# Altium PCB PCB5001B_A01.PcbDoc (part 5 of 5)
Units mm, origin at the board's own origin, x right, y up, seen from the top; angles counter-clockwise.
Board outline 115 x 60 mm, 6 copper layers (Top Layer, GND Layer 2, Signal Layer 3, Signal Layer 4, VCC Layer 5, Bottom Layer), stack 1.555 mm thick; 370 components, 274 nets, 1305 pads, 1129 vias.
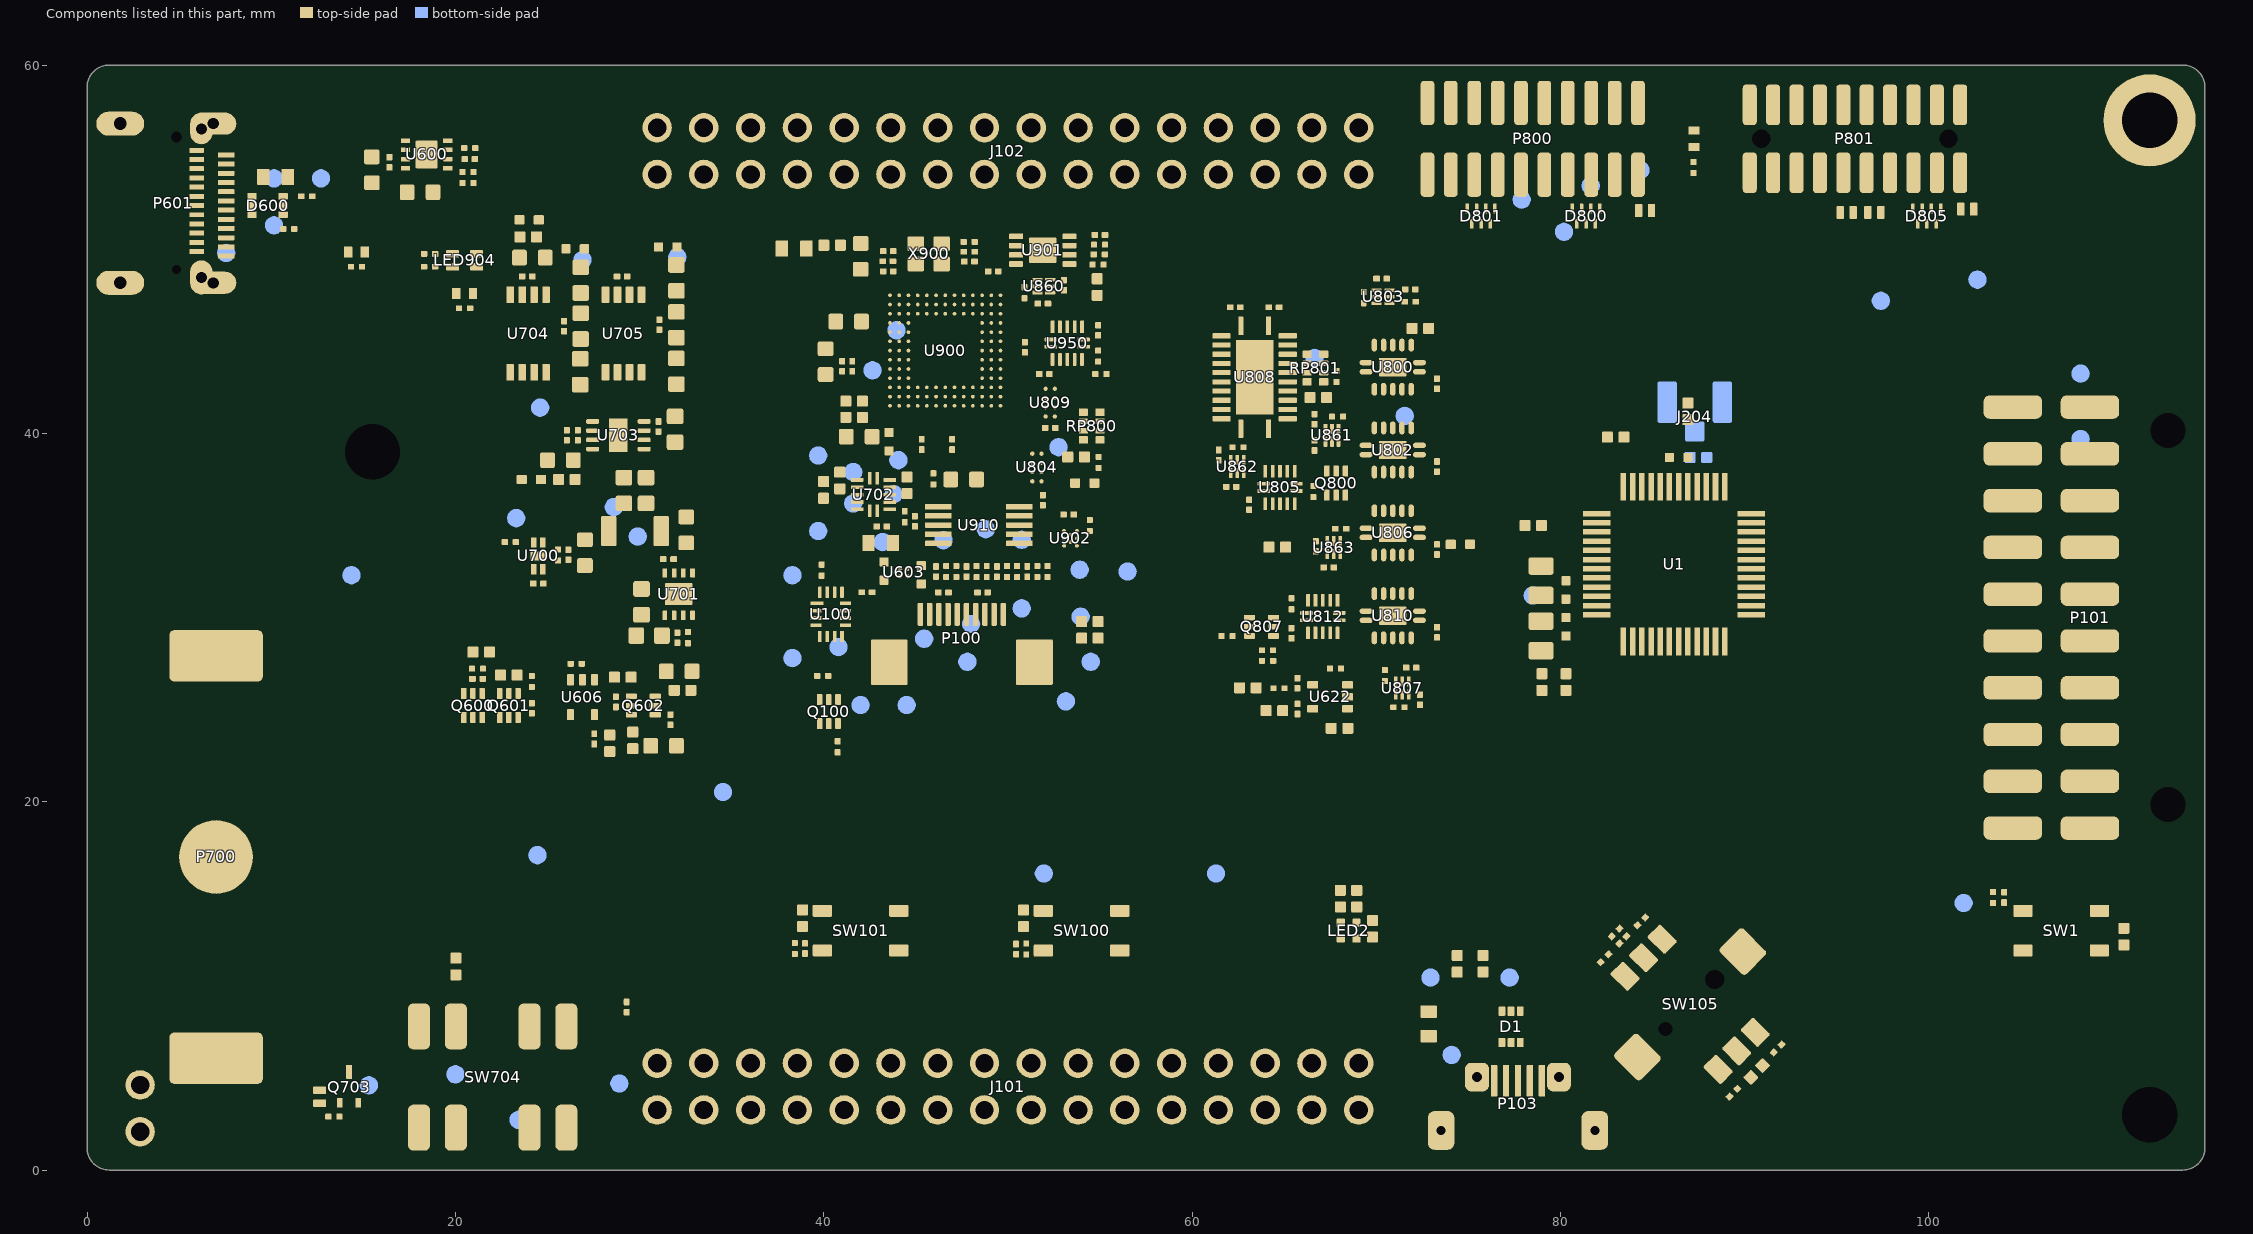
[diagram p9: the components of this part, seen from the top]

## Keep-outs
Bottom Layer:
  region: 12.7,54.35 cw(c12.7,53.85) 13.2,53.85 cw(c12.7,53.85) 12.7,53.35 cw(c12.7,53.85) 12.2,53.85 cw(c12.7,53.85)
  region: 32.691,5.802 ccw(c33.491,5.802) 33.491,5.002 ccw(c33.491,5.802) 34.291,5.802 ccw(c33.491,5.802) 33.491,6.602 ccw(c33.491,5.802)
  region: 35.231,5.802 ccw(c36.031,5.802) 36.031,5.002 ccw(c36.031,5.802) 36.831,5.802 ccw(c36.031,5.802) 36.031,6.602 ccw(c36.031,5.802)
  region: 37.771,5.802 ccw(c38.571,5.802) 38.571,5.002 ccw(c38.571,5.802) 39.371,5.802 ccw(c38.571,5.802) 38.571,6.602 ccw(c38.571,5.802)
  region: 40.311,5.802 ccw(c41.111,5.802) 41.111,5.002 ccw(c41.111,5.802) 41.911,5.802 ccw(c41.111,5.802) 41.111,6.602 ccw(c41.111,5.802)
  region: 42.851,5.802 ccw(c43.651,5.802) 43.651,5.002 ccw(c43.651,5.802) 44.451,5.802 ccw(c43.651,5.802) 43.651,6.602 ccw(c43.651,5.802)
  region: 45.391,5.802 ccw(c46.191,5.802) 46.191,5.002 ccw(c46.191,5.802) 46.991,5.802 ccw(c46.191,5.802) 46.191,6.602 ccw(c46.191,5.802)
  region: 47.931,5.802 ccw(c48.731,5.802) 48.731,5.002 ccw(c48.731,5.802) 49.531,5.802 ccw(c48.731,5.802) 48.731,6.602 ccw(c48.731,5.802)
  region: 50.471,5.802 ccw(c51.271,5.802) 51.271,5.002 ccw(c51.271,5.802) 52.071,5.802 ccw(c51.271,5.802) 51.271,6.602 ccw(c51.271,5.802)
  region: 53.011,5.802 ccw(c53.811,5.802) 53.811,5.002 ccw(c53.811,5.802) 54.611,5.802 ccw(c53.811,5.802) 53.811,6.602 ccw(c53.811,5.802)
  region: 55.551,5.802 ccw(c56.351,5.802) 56.351,5.002 ccw(c56.351,5.802) 57.151,5.802 ccw(c56.351,5.802) 56.351,6.602 ccw(c56.351,5.802)
  region: 58.091,5.802 ccw(c58.891,5.802) 58.891,5.002 ccw(c58.891,5.802) 59.691,5.802 ccw(c58.891,5.802) 58.891,6.602 ccw(c58.891,5.802)
  region: 60.631,5.802 ccw(c61.431,5.802) 61.431,5.002 ccw(c61.431,5.802) 62.231,5.802 ccw(c61.431,5.802) 61.431,6.602 ccw(c61.431,5.802)
  region: 63.171,5.802 ccw(c63.971,5.802) 63.971,5.002 ccw(c63.971,5.802) 64.771,5.802 ccw(c63.971,5.802) 63.971,6.602 ccw(c63.971,5.802)
  region: 65.711,5.802 ccw(c66.511,5.802) 66.511,5.002 ccw(c66.511,5.802) 67.311,5.802 ccw(c66.511,5.802) 66.511,6.602 ccw(c66.511,5.802)
  region: 68.251,5.802 ccw(c69.051,5.802) 69.051,5.002 ccw(c69.051,5.802) 69.851,5.802 ccw(c69.051,5.802) 69.051,6.602 ccw(c69.051,5.802)
  region: 30.151,5.802 ccw(c30.951,5.802) 30.951,5.002 ccw(c30.951,5.802) 31.751,5.802 ccw(c30.951,5.802) 30.951,6.602 ccw(c30.951,5.802)
  region: 30.151,3.262 ccw(c30.951,3.262) 30.951,2.462 ccw(c30.951,3.262) 31.751,3.262 ccw(c30.951,3.262) 30.951,4.062 ccw(c30.951,3.262)
  region: 30.151,3.262 ccw(c30.951,3.262) 30.951,2.462 ccw(c30.951,3.262) 31.751,3.262 ccw(c30.951,3.262) 30.951,4.062 ccw(c30.951,3.262)
  region: 32.691,3.262 ccw(c33.491,3.262) 33.491,2.462 ccw(c33.491,3.262) 34.291,3.262 ccw(c33.491,3.262) 33.491,4.062 ccw(c33.491,3.262)
  region: 35.231,3.262 ccw(c36.031,3.262) 36.031,2.462 ccw(c36.031,3.262) 36.831,3.262 ccw(c36.031,3.262) 36.031,4.062 ccw(c36.031,3.262)
  region: 37.771,3.262 ccw(c38.571,3.262) 38.571,2.462 ccw(c38.571,3.262) 39.371,3.262 ccw(c38.571,3.262) 38.571,4.062 ccw(c38.571,3.262)
  region: 40.311,3.262 ccw(c41.111,3.262) 41.111,2.462 ccw(c41.111,3.262) 41.911,3.262 ccw(c41.111,3.262) 41.111,4.062 ccw(c41.111,3.262)
  region: 42.851,3.262 ccw(c43.651,3.262) 43.651,2.462 ccw(c43.651,3.262) 44.451,3.262 ccw(c43.651,3.262) 43.651,4.062 ccw(c43.651,3.262)
  region: 45.391,3.262 ccw(c46.191,3.262) 46.191,2.462 ccw(c46.191,3.262) 46.991,3.262 ccw(c46.191,3.262) 46.191,4.062 ccw(c46.191,3.262)
  region: 47.931,3.262 ccw(c48.731,3.262) 48.731,2.462 ccw(c48.731,3.262) 49.531,3.262 ccw(c48.731,3.262) 48.731,4.062 ccw(c48.731,3.262)
  region: 50.471,3.262 ccw(c51.271,3.262) 51.271,2.462 ccw(c51.271,3.262) 52.071,3.262 ccw(c51.271,3.262) 51.271,4.062 ccw(c51.271,3.262)
  region: 53.011,3.262 ccw(c53.811,3.262) 53.811,2.462 ccw(c53.811,3.262) 54.611,3.262 ccw(c53.811,3.262) 53.811,4.062 ccw(c53.811,3.262)
  region: 55.551,3.262 ccw(c56.351,3.262) 56.351,2.462 ccw(c56.351,3.262) 57.151,3.262 ccw(c56.351,3.262) 56.351,4.062 ccw(c56.351,3.262)
  region: 58.091,3.262 ccw(c58.891,3.262) 58.891,2.462 ccw(c58.891,3.262) 59.691,3.262 ccw(c58.891,3.262) 58.891,4.062 ccw(c58.891,3.262)
  region: 60.631,3.262 ccw(c61.431,3.262) 61.431,2.462 ccw(c61.431,3.262) 62.231,3.262 ccw(c61.431,3.262) 61.431,4.062 ccw(c61.431,3.262)
  region: 63.171,3.262 ccw(c63.971,3.262) 63.971,2.462 ccw(c63.971,3.262) 64.771,3.262 ccw(c63.971,3.262) 63.971,4.062 ccw(c63.971,3.262)
  region: 65.711,3.262 ccw(c66.511,3.262) 66.511,2.462 ccw(c66.511,3.262) 67.311,3.262 ccw(c66.511,3.262) 66.511,4.062 ccw(c66.511,3.262)
  region: 68.251,3.262 ccw(c69.051,3.262) 69.051,2.462 ccw(c69.051,3.262) 69.851,3.262 ccw(c69.051,3.262) 69.051,4.062 ccw(c69.051,3.262)
  region: 32.691,56.602 ccw(c33.491,56.602) 33.491,55.802 ccw(c33.491,56.602) 34.291,56.602 ccw(c33.491,56.602) 33.491,57.402 ccw(c33.491,56.602)
  region: 35.231,56.602 ccw(c36.031,56.602) 36.031,55.802 ccw(c36.031,56.602) 36.831,56.602 ccw(c36.031,56.602) 36.031,57.402 ccw(c36.031,56.602)
  region: 37.771,56.602 ccw(c38.571,56.602) 38.571,55.802 ccw(c38.571,56.602) 39.371,56.602 ccw(c38.571,56.602) 38.571,57.402 ccw(c38.571,56.602)
  region: 40.311,56.602 ccw(c41.111,56.602) 41.111,55.802 ccw(c41.111,56.602) 41.911,56.602 ccw(c41.111,56.602) 41.111,57.402 ccw(c41.111,56.602)
  region: 42.851,56.602 ccw(c43.651,56.602) 43.651,55.802 ccw(c43.651,56.602) 44.451,56.602 ccw(c43.651,56.602) 43.651,57.402 ccw(c43.651,56.602)
  region: 45.391,56.602 ccw(c46.191,56.602) 46.191,55.802 ccw(c46.191,56.602) 46.991,56.602 ccw(c46.191,56.602) 46.191,57.402 ccw(c46.191,56.602)
  region: 47.931,56.602 ccw(c48.731,56.602) 48.731,55.802 ccw(c48.731,56.602) 49.531,56.602 ccw(c48.731,56.602) 48.731,57.402 ccw(c48.731,56.602)
  region: 50.471,56.602 ccw(c51.271,56.602) 51.271,55.802 ccw(c51.271,56.602) 52.071,56.602 ccw(c51.271,56.602) 51.271,57.402 ccw(c51.271,56.602)
  region: 53.011,56.602 ccw(c53.811,56.602) 53.811,55.802 ccw(c53.811,56.602) 54.611,56.602 ccw(c53.811,56.602) 53.811,57.402 ccw(c53.811,56.602)
  region: 55.551,56.602 ccw(c56.351,56.602) 56.351,55.802 ccw(c56.351,56.602) 57.151,56.602 ccw(c56.351,56.602) 56.351,57.402 ccw(c56.351,56.602)
  region: 58.091,56.602 ccw(c58.891,56.602) 58.891,55.802 ccw(c58.891,56.602) 59.691,56.602 ccw(c58.891,56.602) 58.891,57.402 ccw(c58.891,56.602)
  region: 60.631,56.602 ccw(c61.431,56.602) 61.431,55.802 ccw(c61.431,56.602) 62.231,56.602 ccw(c61.431,56.602) 61.431,57.402 ccw(c61.431,56.602)
  region: 63.171,56.602 ccw(c63.971,56.602) 63.971,55.802 ccw(c63.971,56.602) 64.771,56.602 ccw(c63.971,56.602) 63.971,57.402 ccw(c63.971,56.602)
  region: 65.711,56.602 ccw(c66.511,56.602) 66.511,55.802 ccw(c66.511,56.602) 67.311,56.602 ccw(c66.511,56.602) 66.511,57.402 ccw(c66.511,56.602)
  region: 68.251,56.602 ccw(c69.051,56.602) 69.051,55.802 ccw(c69.051,56.602) 69.851,56.602 ccw(c69.051,56.602) 69.051,57.402 ccw(c69.051,56.602)
  region: 30.151,56.602 ccw(c30.951,56.602) 30.951,55.802 ccw(c30.951,56.602) 31.751,56.602 ccw(c30.951,56.602) 30.951,57.402 ccw(c30.951,56.602)
  region: 30.151,54.062 ccw(c30.951,54.062) 30.951,53.262 ccw(c30.951,54.062) 31.751,54.062 ccw(c30.951,54.062) 30.951,54.862 ccw(c30.951,54.062)
  region: 30.151,54.062 ccw(c30.951,54.062) 30.951,53.262 ccw(c30.951,54.062) 31.751,54.062 ccw(c30.951,54.062) 30.951,54.862 ccw(c30.951,54.062)
  region: 32.691,54.062 ccw(c33.491,54.062) 33.491,53.262 ccw(c33.491,54.062) 34.291,54.062 ccw(c33.491,54.062) 33.491,54.862 ccw(c33.491,54.062)
  region: 35.231,54.062 ccw(c36.031,54.062) 36.031,53.262 ccw(c36.031,54.062) 36.831,54.062 ccw(c36.031,54.062) 36.031,54.862 ccw(c36.031,54.062)
  region: 37.771,54.062 ccw(c38.571,54.062) 38.571,53.262 ccw(c38.571,54.062) 39.371,54.062 ccw(c38.571,54.062) 38.571,54.862 ccw(c38.571,54.062)
  region: 40.311,54.062 ccw(c41.111,54.062) 41.111,53.262 ccw(c41.111,54.062) 41.911,54.062 ccw(c41.111,54.062) 41.111,54.862 ccw(c41.111,54.062)
  region: 42.851,54.062 ccw(c43.651,54.062) 43.651,53.262 ccw(c43.651,54.062) 44.451,54.062 ccw(c43.651,54.062) 43.651,54.862 ccw(c43.651,54.062)
  region: 45.391,54.062 ccw(c46.191,54.062) 46.191,53.262 ccw(c46.191,54.062) 46.991,54.062 ccw(c46.191,54.062) 46.191,54.862 ccw(c46.191,54.062)
  region: 47.931,54.062 ccw(c48.731,54.062) 48.731,53.262 ccw(c48.731,54.062) 49.531,54.062 ccw(c48.731,54.062) 48.731,54.862 ccw(c48.731,54.062)
  region: 50.471,54.062 ccw(c51.271,54.062) 51.271,53.262 ccw(c51.271,54.062) 52.071,54.062 ccw(c51.271,54.062) 51.271,54.862 ccw(c51.271,54.062)
  region: 53.011,54.062 ccw(c53.811,54.062) 53.811,53.262 ccw(c53.811,54.062) 54.611,54.062 ccw(c53.811,54.062) 53.811,54.862 ccw(c53.811,54.062)
  region: 55.551,54.062 ccw(c56.351,54.062) 56.351,53.262 ccw(c56.351,54.062) 57.151,54.062 ccw(c56.351,54.062) 56.351,54.862 ccw(c56.351,54.062)
  region: 58.091,54.062 ccw(c58.891,54.062) 58.891,53.262 ccw(c58.891,54.062) 59.691,54.062 ccw(c58.891,54.062) 58.891,54.862 ccw(c58.891,54.062)
  region: 60.631,54.062 ccw(c61.431,54.062) 61.431,53.262 ccw(c61.431,54.062) 62.231,54.062 ccw(c61.431,54.062) 61.431,54.862 ccw(c61.431,54.062)
  region: 63.171,54.062 ccw(c63.971,54.062) 63.971,53.262 ccw(c63.971,54.062) 64.771,54.062 ccw(c63.971,54.062) 63.971,54.862 ccw(c63.971,54.062)
  region: 65.711,54.062 ccw(c66.511,54.062) 66.511,53.262 ccw(c66.511,54.062) 67.311,54.062 ccw(c66.511,54.062) 66.511,54.862 ccw(c66.511,54.062)
  region: 68.251,54.062 ccw(c69.051,54.062) 69.051,53.262 ccw(c69.051,54.062) 69.851,54.062 ccw(c69.051,54.062) 69.051,54.862 ccw(c69.051,54.062)
  region: 45.391,54.062 ccw(c46.191,54.062) 46.191,53.262 ccw(c46.191,54.062) 46.991,54.062 ccw(c46.191,54.062) 46.191,54.862 ccw(c46.191,54.062)
  region: 42.851,54.062 ccw(c43.651,54.062) 43.651,53.262 ccw(c43.651,54.062) 44.451,54.062 ccw(c43.651,54.062) 43.651,54.862 ccw(c43.651,54.062)
  region: 40.311,54.062 ccw(c41.111,54.062) 41.111,53.262 ccw(c41.111,54.062) 41.911,54.062 ccw(c41.111,54.062) 41.111,54.862 ccw(c41.111,54.062)
  region: 37.771,54.062 ccw(c38.571,54.062) 38.571,53.262 ccw(c38.571,54.062) 39.371,54.062 ccw(c38.571,54.062) 38.571,54.862 ccw(c38.571,54.062)
  region: 35.231,54.062 ccw(c36.031,54.062) 36.031,53.262 ccw(c36.031,54.062) 36.831,54.062 ccw(c36.031,54.062) 36.031,54.862 ccw(c36.031,54.062)
  region: 32.691,54.062 ccw(c33.491,54.062) 33.491,53.262 ccw(c33.491,54.062) 34.291,54.062 ccw(c33.491,54.062) 33.491,54.862 ccw(c33.491,54.062)
  region: 30.151,54.062 ccw(c30.951,54.062) 30.951,53.262 ccw(c30.951,54.062) 31.751,54.062 ccw(c30.951,54.062) 30.951,54.862 ccw(c30.951,54.062)
  region: 30.151,54.062 ccw(c30.951,54.062) 30.951,53.262 ccw(c30.951,54.062) 31.751,54.062 ccw(c30.951,54.062) 30.951,54.862 ccw(c30.951,54.062)
  region: 30.151,56.602 ccw(c30.951,56.602) 30.951,55.802 ccw(c30.951,56.602) 31.751,56.602 ccw(c30.951,56.602) 30.951,57.402 ccw(c30.951,56.602)
  region: 45.391,56.602 ccw(c46.191,56.602) 46.191,55.802 ccw(c46.191,56.602) 46.991,56.602 ccw(c46.191,56.602) 46.191,57.402 ccw(c46.191,56.602)
  region: 42.851,56.602 ccw(c43.651,56.602) 43.651,55.802 ccw(c43.651,56.602) 44.451,56.602 ccw(c43.651,56.602) 43.651,57.402 ccw(c43.651,56.602)
  region: 40.311,56.602 ccw(c41.111,56.602) 41.111,55.802 ccw(c41.111,56.602) 41.911,56.602 ccw(c41.111,56.602) 41.111,57.402 ccw(c41.111,56.602)
  region: 37.771,56.602 ccw(c38.571,56.602) 38.571,55.802 ccw(c38.571,56.602) 39.371,56.602 ccw(c38.571,56.602) 38.571,57.402 ccw(c38.571,56.602)
  region: 35.231,56.602 ccw(c36.031,56.602) 36.031,55.802 ccw(c36.031,56.602) 36.831,56.602 ccw(c36.031,56.602) 36.031,57.402 ccw(c36.031,56.602)
  region: 32.691,56.602 ccw(c33.491,56.602) 33.491,55.802 ccw(c33.491,56.602) 34.291,56.602 ccw(c33.491,56.602) 33.491,57.402 ccw(c33.491,56.602)
  region: 68.251,3.262 ccw(c69.051,3.262) 69.051,2.462 ccw(c69.051,3.262) 69.851,3.262 ccw(c69.051,3.262) 69.051,4.062 ccw(c69.051,3.262)
  region: 65.711,3.262 ccw(c66.511,3.262) 66.511,2.462 ccw(c66.511,3.262) 67.311,3.262 ccw(c66.511,3.262) 66.511,4.062 ccw(c66.511,3.262)
  region: 60.631,3.262 ccw(c61.431,3.262) 61.431,2.462 ccw(c61.431,3.262) 62.231,3.262 ccw(c61.431,3.262) 61.431,4.062 ccw(c61.431,3.262)
  region: 58.091,3.262 ccw(c58.891,3.262) 58.891,2.462 ccw(c58.891,3.262) 59.691,3.262 ccw(c58.891,3.262) 58.891,4.062 ccw(c58.891,3.262)
  region: 40.311,3.262 ccw(c41.111,3.262) 41.111,2.462 ccw(c41.111,3.262) 41.911,3.262 ccw(c41.111,3.262) 41.111,4.062 ccw(c41.111,3.262)
  region: 37.771,3.262 ccw(c38.571,3.262) 38.571,2.462 ccw(c38.571,3.262) 39.371,3.262 ccw(c38.571,3.262) 38.571,4.062 ccw(c38.571,3.262)
  region: 35.231,3.262 ccw(c36.031,3.262) 36.031,2.462 ccw(c36.031,3.262) 36.831,3.262 ccw(c36.031,3.262) 36.031,4.062 ccw(c36.031,3.262)
  region: 32.691,3.262 ccw(c33.491,3.262) 33.491,2.462 ccw(c33.491,3.262) 34.291,3.262 ccw(c33.491,3.262) 33.491,4.062 ccw(c33.491,3.262)
  region: 30.151,3.262 ccw(c30.951,3.262) 30.951,2.462 ccw(c30.951,3.262) 31.751,3.262 ccw(c30.951,3.262) 30.951,4.062 ccw(c30.951,3.262)
  region: 30.151,3.262 ccw(c30.951,3.262) 30.951,2.462 ccw(c30.951,3.262) 31.751,3.262 ccw(c30.951,3.262) 30.951,4.062 ccw(c30.951,3.262)
  region: 30.151,5.802 ccw(c30.951,5.802) 30.951,5.002 ccw(c30.951,5.802) 31.751,5.802 ccw(c30.951,5.802) 30.951,6.602 ccw(c30.951,5.802)
  region: 68.251,5.802 ccw(c69.051,5.802) 69.051,5.002 ccw(c69.051,5.802) 69.851,5.802 ccw(c69.051,5.802) 69.051,6.602 ccw(c69.051,5.802)
  region: 65.711,5.802 ccw(c66.511,5.802) 66.511,5.002 ccw(c66.511,5.802) 67.311,5.802 ccw(c66.511,5.802) 66.511,6.602 ccw(c66.511,5.802)
  region: 63.171,5.802 ccw(c63.971,5.802) 63.971,5.002 ccw(c63.971,5.802) 64.771,5.802 ccw(c63.971,5.802) 63.971,6.602 ccw(c63.971,5.802)
  region: 60.631,5.802 ccw(c61.431,5.802) 61.431,5.002 ccw(c61.431,5.802) 62.231,5.802 ccw(c61.431,5.802) 61.431,6.602 ccw(c61.431,5.802)
  region: 58.091,5.802 ccw(c58.891,5.802) 58.891,5.002 ccw(c58.891,5.802) 59.691,5.802 ccw(c58.891,5.802) 58.891,6.602 ccw(c58.891,5.802)
  region: 40.311,5.802 ccw(c41.111,5.802) 41.111,5.002 ccw(c41.111,5.802) 41.911,5.802 ccw(c41.111,5.802) 41.111,6.602 ccw(c41.111,5.802)
  region: 37.771,5.802 ccw(c38.571,5.802) 38.571,5.002 ccw(c38.571,5.802) 39.371,5.802 ccw(c38.571,5.802) 38.571,6.602 ccw(c38.571,5.802)
  region: 35.231,5.802 ccw(c36.031,5.802) 36.031,5.002 ccw(c36.031,5.802) 36.831,5.802 ccw(c36.031,5.802) 36.031,6.602 ccw(c36.031,5.802)
  region: 32.691,5.802 ccw(c33.491,5.802) 33.491,5.002 ccw(c33.491,5.802) 34.291,5.802 ccw(c33.491,5.802) 33.491,6.602 ccw(c33.491,5.802)
  region: 103.5,19 cw(c103.5,18.5) 104,18.5 cw(c103.5,18.5) 103.5,18 cw(c103.5,18.5) 103,18.5 cw(c103.5,18.5)
  region: 108.25,40.2 cw(c108.25,39.699) 108.75,39.7 cw(c108.25,39.7) 108.25,39.2 cw(c108.25,39.7) 107.75,39.7 cw(c108.25,39.699)
  region: 108.25,43.748 cw(c108.25,43.248) 108.75,43.248 cw(c108.25,43.248) 108.25,42.748 cw(c108.25,43.248) 107.75,43.248 cw(c108.25,43.248)
  region: 107,54.2 cw(c107,53.7) 107.5,53.7 cw(c107,53.7) 107,53.2 cw(c107,53.7) 106.5,53.7 cw(c107,53.7)
  region: 105.4,52.498 cw(c105.4,51.998) 105.9,51.998 cw(c105.4,51.998) 105.4,51.498 cw(c105.4,51.998) 104.9,51.998 cw(c105.4,51.998)
  region: 104.45,54.2 cw(c104.45,53.7) 104.95,53.7 cw(c104.45,53.7) 104.45,53.2 cw(c104.45,53.7) 103.95,53.7 cw(c104.45,53.7)
  region: 103.399,52.498 cw(c103.399,51.998) 103.899,51.998 cw(c103.399,51.998) 103.399,51.498 cw(c103.399,51.998) 102.899,51.998 cw(c103.399,51.998)
  region: 102.649,48.848 cw(c102.649,48.348) 103.149,48.348 cw(c102.649,48.348) 102.649,47.848 cw(c102.649,48.348) 102.149,48.348 cw(c102.649,48.348)
  region: 97.399,47.7 cw(c97.399,47.2) 97.899,47.2 cw(c97.399,47.2) 97.399,46.7 cw(c97.399,47.2) 96.899,47.2 cw(c97.399,47.2)
  region: 92.525,52.432 cw(c92.525,51.932) 93.025,51.932 cw(c92.525,51.932) 92.525,51.432 cw(c92.525,51.932) 92.025,51.932 cw(c92.525,51.932)
  region: 93.541,54.21 cw(c93.541,53.71) 94.041,53.71 cw(c93.541,53.71) 93.541,53.21 cw(c93.541,53.71) 93.041,53.71 cw(c93.541,53.71)
  region: 90.493,52.432 cw(c90.493,51.932) 90.993,51.932 cw(c90.493,51.932) 90.493,51.432 cw(c90.493,51.932) 89.993,51.932 cw(c90.493,51.932)
  region: 88.461,52.432 cw(c88.461,51.932) 88.961,51.932 cw(c88.461,51.932) 88.461,51.432 cw(c88.461,51.932) 87.961,51.932 cw(c88.461,51.932)
  region: 89.477,54.21 cw(c89.477,53.71) 89.977,53.71 cw(c89.477,53.71) 89.477,53.21 cw(c89.477,53.71) 88.977,53.71 cw(c89.477,53.71)
  region: 87.466,54.206 cw(c87.467,53.706) 87.967,53.706 cw(c87.466,53.707) 87.466,53.206 cw(c87.466,53.706) 86.967,53.706 cw(c87.467,53.706)
  region: 84.349,54.799 cw(c84.349,54.299) 84.849,54.3 cw(c84.349,54.3) 84.349,53.799 cw(c84.349,54.299) 83.849,54.299 cw(c84.349,54.299)
  region: 85.4,52.198 cw(c85.4,51.698) 85.9,51.699 cw(c85.4,51.699) 85.4,51.199 cw(c85.4,51.698) 84.9,51.698 cw(c85.4,51.698)
  region: 93.449,42.798 cw(c93.45,42.298) 93.95,42.298 cw(c93.449,42.298) 93.449,41.798 cw(c93.449,42.298) 92.949,42.298 cw(c93.45,42.298)
  region: 86.15,40.05 cw(c86.15,39.55) 86.65,39.55 cw(c86.149,39.55) 86.149,39.05 cw(c86.149,39.55) 85.65,39.55 cw(c86.15,39.55)
  region: 81.649,53.949 cw(c81.649,53.449) 82.149,53.449 cw(c81.649,53.449) 81.649,52.949 cw(c81.649,53.449) 81.149,53.449 cw(c81.649,53.448)
  region: 77.9,53.199 cw(c77.9,52.699) 78.4,52.699 cw(c77.9,52.699) 77.9,52.199 cw(c77.9,52.699) 77.4,52.699 cw(c77.9,52.699)
  region: 80.201,51.449 cw(c80.201,50.949) 80.701,50.949 cw(c80.201,50.949) 80.201,50.449 cw(c80.201,50.949) 79.701,50.949 cw(c80.201,50.949)
  region: 77.399,48.498 cw(c77.399,47.998) 77.899,47.998 cw(c77.399,47.998) 77.399,47.498 cw(c77.399,47.998) 76.899,47.998 cw(c77.399,47.998)
  region: 75.4,48.498 cw(c75.4,47.998) 75.9,47.998 cw(c75.4,47.998) 75.4,47.498 cw(c75.4,47.998) 74.9,47.998 cw(c75.4,47.998)
  region: 73.399,48.498 cw(c73.399,47.998) 73.899,47.998 cw(c73.399,47.998) 73.399,47.498 cw(c73.399,47.998) 72.899,47.998 cw(c73.399,47.998)
  region: 77.399,46.298 cw(c77.399,45.798) 77.899,45.798 cw(c77.399,45.798) 77.399,45.298 cw(c77.399,45.798) 76.899,45.798 cw(c77.399,45.798)
  region: 75.4,46.298 cw(c75.4,45.798) 75.9,45.798 cw(c75.4,45.798) 75.4,45.298 cw(c75.4,45.798) 74.9,45.798 cw(c75.4,45.798)
  region: 73.399,46.298 cw(c73.399,45.798) 73.899,45.798 cw(c73.399,45.798) 73.399,45.298 cw(c73.399,45.798) 72.899,45.798 cw(c73.399,45.798)
  region: 71.4,46.298 cw(c71.4,45.798) 71.9,45.798 cw(c71.4,45.798) 71.4,45.298 cw(c71.4,45.798) 70.9,45.798 cw(c71.4,45.798)
  region: 73.399,43.598 cw(c73.399,43.098) 73.899,43.098 cw(c73.399,43.098) 73.399,42.598 cw(c73.399,43.098) 72.899,43.098 cw(c73.399,43.098)
  region: 71.55,41.449 cw(c71.55,40.949) 72.05,40.949 cw(c71.55,40.949) 71.55,40.449 cw(c71.55,40.949) 71.05,40.949 cw(c71.55,40.949)
  region: 66.65,44.599 cw(c66.65,44.099) 67.15,44.099 cw(c66.65,44.099) 66.65,43.599 cw(c66.65,44.099) 66.15,44.099 cw(c66.65,44.099)
  region: 94.199,12.348 cw(c94.199,11.848) 94.699,11.848 cw(c94.199,11.849) 94.199,11.348 cw(c94.199,11.848) 93.699,11.848 cw(c94.199,11.848)
  region: 96.8,11.8 cw(c96.8,11.3) 97.3,11.3 cw(c96.8,11.3) 96.8,10.8 cw(c96.8,11.3) 96.3,11.3 cw(c96.8,11.3)
  region: 93.249,9.948 cw(c93.249,9.448) 93.749,9.448 cw(c93.249,9.448) 93.249,8.948 cw(c93.249,9.448) 92.749,9.448 cw(c93.249,9.448)
  region: 96.5,9.148 cw(c96.5,8.648) 97,8.648 cw(c96.5,8.648) 96.5,8.148 cw(c96.5,8.648) 96,8.648 cw(c96.5,8.648)
  region: 95.7,6.55 cw(c95.7,6.05) 96.2,6.05 cw(c95.7,6.05) 95.7,5.55 cw(c95.7,6.05) 95.2,6.05 cw(c95.7,6.049)
  region: 93.249,7.398 cw(c93.249,6.898) 93.749,6.898 cw(c93.249,6.898) 93.249,6.398 cw(c93.249,6.898) 92.749,6.898 cw(c93.249,6.898)
  region: 81.499,10.949 cw(c81.499,10.449) 81.999,10.449 cw(c81.499,10.449) 81.499,9.949 cw(c81.499,10.449) 80.999,10.449 cw(c81.499,10.449)
  region: 77.249,10.949 cw(c77.249,10.449) 77.749,10.449 cw(c77.249,10.449) 77.249,9.949 cw(c77.249,10.449) 76.749,10.449 cw(c77.249,10.449)
  region: 72.949,10.949 cw(c72.949,10.449) 73.449,10.449 cw(c72.949,10.449) 72.949,9.949 cw(c72.949,10.449) 72.449,10.449 cw(c72.949,10.449)
  region: 74.1,6.748 cw(c74.1,6.248) 74.6,6.248 cw(c74.1,6.248) 74.1,5.748 cw(c74.1,6.248) 73.6,6.248 cw(c74.1,6.248)
  region: 54.674,41.624 cw(c54.674,41.124) 55.174,41.125 cw(c54.674,41.125) 54.674,40.625 cw(c54.674,41.124) 54.174,41.124 cw(c54.674,41.124)
  region: 52.749,39.75 cw(c52.749,39.25) 53.249,39.25 cw(c52.748,39.25) 52.748,38.75 cw(c52.748,39.25) 52.249,39.25 cw(c52.749,39.25)
  region: 50.75,34.723 cw(c50.75,34.223) 51.25,34.223 cw(c50.749,34.223) 50.75,33.723 cw(c50.75,34.223) 50.25,34.223 cw(c50.75,34.223)
  region: 53.899,33.098 cw(c53.899,32.598) 54.399,32.598 cw(c53.899,32.598) 53.899,32.098 cw(c53.899,32.598) 53.399,32.598 cw(c53.899,32.598)
  region: 50.75,31 cw(c50.75,30.5) 51.25,30.5 cw(c50.749,30.5) 50.75,30 cw(c50.75,30.5) 50.25,30.5 cw(c50.75,30.5)
  region: 53.95,30.55 cw(c53.95,30.05) 54.45,30.05 cw(c53.95,30.05) 53.95,29.55 cw(c53.95,30.05) 53.45,30.05 cw(c53.95,30.05)
  region: 54.499,28.099 cw(c54.499,27.599) 54.999,27.599 cw(c54.498,27.599) 54.499,27.099 cw(c54.499,27.599) 53.999,27.599 cw(c54.499,27.599)
  region: 51.799,28.099 cw(c51.799,27.599) 52.299,27.599 cw(c51.798,27.599) 51.799,27.099 cw(c51.799,27.599) 51.299,27.599 cw(c51.799,27.599)
  region: 53.15,25.95 cw(c53.15,25.45) 53.65,25.45 cw(c53.15,25.45) 53.15,24.95 cw(c53.15,25.45) 52.65,25.45 cw(c53.15,25.45)
  region: 47.999,30.149 cw(c47.999,29.649) 48.499,29.649 cw(c47.999,29.649) 47.999,29.149 cw(c47.999,29.649) 47.499,29.649 cw(c47.999,29.649)
  region: 45.449,29.349 cw(c45.449,28.849) 45.949,28.849 cw(c45.448,28.849) 45.449,28.349 cw(c45.449,28.849) 44.949,28.849 cw(c45.449,28.849)
  region: 47,25.749 cw(c47.001,25.249) 47.501,25.25 cw(c47,25.25) 47,24.75 cw(c47,25.249) 46.501,25.249 cw(c47.001,25.249)
  region: 43.249,28 cw(c43.249,27.5) 43.749,27.5 cw(c43.249,27.5) 43.249,27 cw(c43.249,27.5) 42.749,27.5 cw(c43.249,27.5)
  region: 44.499,25.749 cw(c44.499,25.249) 44.999,25.25 cw(c44.499,25.25) 44.499,24.75 cw(c44.499,25.249) 43.999,25.249 cw(c44.499,25.249)
  region: 41.999,25.749 cw(c41.999,25.249) 42.499,25.25 cw(c41.999,25.25) 41.999,24.75 cw(c41.999,25.249) 41.499,25.249 cw(c41.999,25.249)
  region: 61.301,16.598 cw(c61.301,16.098) 61.801,16.098 cw(c61.301,16.098) 61.301,15.598 cw(c61.301,16.098) 60.801,16.098 cw(c61.301,16.098)
  region: 51.951,16.598 cw(c51.951,16.098) 52.451,16.098 cw(c51.951,16.098) 51.951,15.598 cw(c51.951,16.098) 51.451,16.098 cw(c51.951,16.098)
  region: 34.524,21.025 cw(c34.524,20.525) 35.024,20.525 cw(c34.524,20.525) 34.524,20.025 cw(c34.524,20.525) 34.024,20.525 cw(c34.524,20.525)
  region: 24.45,17.599 cw(c24.45,17.099) 24.95,17.099 cw(c24.45,17.099) 24.45,16.599 cw(c24.45,17.099) 23.95,17.099 cw(c24.45,17.098)
  region: 15.649,26.448 cw(c15.649,25.948) 16.149,25.948 cw(c15.649,25.948) 15.649,25.448 cw(c15.649,25.948) 15.149,25.948 cw(c15.649,25.948)
  region: 12.05,26.448 cw(c12.05,25.948) 12.55,25.948 cw(c12.05,25.948) 12.05,25.448 cw(c12.05,25.948) 11.55,25.948 cw(c12.05,25.948)
  region: 12.025,29.773 cw(c12.025,29.273) 12.525,29.273 cw(c12.025,29.273) 12.025,28.773 cw(c12.025,29.273) 11.525,29.273 cw(c12.025,29.273)
  region: 9.475,29.798 cw(c9.475,29.298) 9.975,29.298 cw(c9.474,29.298) 9.475,28.798 cw(c9.475,29.298) 8.975,29.298 cw(c9.475,29.298)
  region: 14.349,32.798 cw(c14.349,32.298) 14.849,32.298 cw(c14.349,32.298) 14.349,31.798 cw(c14.349,32.298) 13.849,32.298 cw(c14.349,32.298)
  region: 10.399,32.249 cw(c10.399,31.749) 10.899,31.749 cw(c10.399,31.75) 10.399,31.249 cw(c10.399,31.749) 9.899,31.749 cw(c10.399,31.749)
  region: 10.399,34.899 cw(c10.399,34.399) 10.899,34.399 cw(c10.399,34.399) 10.399,33.899 cw(c10.399,34.399) 9.899,34.399 cw(c10.399,34.398)
  region: 18.446,49.044 cw(c18.446,48.544) 18.946,48.544 cw(c18.446,48.544) 18.446,48.044 cw(c18.446,48.544) 17.946,48.544 cw(c18.446,48.544)
  region: 15.906,50.314 cw(c15.906,49.814) 16.406,49.814 cw(c15.906,49.814) 15.906,49.314 cw(c15.906,49.814) 15.406,49.814 cw(c15.906,49.814)
  region: 18.446,51.584 cw(c18.446,51.084) 18.946,51.084 cw(c18.446,51.084) 18.446,50.584 cw(c18.446,51.084) 17.946,51.084 cw(c18.446,51.084)
  region: 15.906,52.854 cw(c15.906,52.354) 16.406,52.354 cw(c15.906,52.354) 15.906,51.854 cw(c15.906,52.354) 15.406,52.354 cw(c15.906,52.354)
  region: 18.446,54.124 cw(c18.446,53.624) 18.946,53.624 cw(c18.446,53.624) 18.446,53.124 cw(c18.446,53.624) 17.946,53.624 cw(c18.446,53.624)
  region: 15.906,55.394 cw(c15.906,54.894) 16.406,54.894 cw(c15.906,54.894) 15.906,54.394 cw(c15.906,54.894) 15.406,54.894 cw(c15.906,54.894)
  region: 10.15,54.35 cw(c10.15,53.85) 10.65,53.85 cw(c10.15,53.85) 10.15,53.35 cw(c10.15,53.85) 9.65,53.85 cw(c10.15,53.85)
  region: 10.15,51.8 cw(c10.15,51.3) 10.65,51.3 cw(c10.15,51.3) 10.15,50.8 cw(c10.15,51.3) 9.65,51.3 cw(c10.15,51.3)
  region: 7.549,50.299 cw(c7.549,49.799) 8.049,49.799 cw(c7.549,49.799) 7.549,49.299 cw(c7.549,49.799) 7.049,49.799 cw(c7.549,49.798)
  region: 24.6,41.899 cw(c24.6,41.399) 25.1,41.399 cw(c24.6,41.399) 24.6,40.899 cw(c24.6,41.399) 24.1,41.399 cw(c24.6,41.399)
  region: 36.249,37.548 cw(c36.249,37.048) 36.749,37.048 cw(c36.249,37.048) 36.249,36.548 cw(c36.249,37.048) 35.749,37.048 cw(c36.249,37.048)
  region: 38.999,37.548 cw(c39,37.048) 39.5,37.048 cw(c38.999,37.048) 38.999,36.548 cw(c38.999,37.048) 38.5,37.048 cw(c39,37.048)
  region: 41.6,38.399 cw(c41.6,37.899) 42.101,37.899 cw(c41.6,37.899) 41.6,37.399 cw(c41.6,37.899) 41.1,37.899 cw(c41.601,37.899)
  region: 44.049,39.049 cw(c44.049,38.549) 44.549,38.549 cw(c44.049,38.549) 44.049,38.049 cw(c44.049,38.549) 43.549,38.549 cw(c44.049,38.549)
  region: 42.649,43.923 cw(c42.65,43.423) 43.15,43.423 cw(c42.649,43.423) 42.649,42.923 cw(c42.649,43.423) 42.149,43.423 cw(c42.65,43.423)
  region: 43.95,46.1 cw(c43.95,45.6) 44.45,45.6 cw(c43.95,45.6) 43.95,45.1 cw(c43.95,45.6) 43.45,45.6 cw(c43.95,45.6)
  region: 18.446,46.504 cw(c18.446,46.004) 18.946,46.004 cw(c18.446,46.004) 18.446,45.504 cw(c18.446,46.004) 17.946,46.004 cw(c18.446,46.004)

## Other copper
Top Layer:
  pour cut-out: 30.625,27.725 30.875,27.475 31.075,27.475 31.075,27.45 31.025,27.4 30.7,27.725
  pour cut-out: 64.725,31.3 64.35,30.925 64.35,30.8 64.449,30.8 64.75,31.101 64.75,31.25
  pour cut-out: 65.452,31.453 65.749,31.75 66,31.75 66,31.65 66.025,31.625 65.825,31.425 65.48,31.425
  pour cut-out: 24.525,49.15 24.315,48.94 24.315,48.839 24.259,48.839 24.109,48.989 24.27,49.15 24.5,49.15
  pour cut-out: 38.15,50.5 38.625,50.5 38.75,50.375 38.65,50.275 38.65,49.55 38.35,49.55 38.15,49.75 38.15,50.475
  pour cut-out: 82.85,36.225 89.575,36.225 89.575,29.525 89.525,29.475 82.825,29.475 82.825,36.2 82.875,36.25
  region net 3V3: 102.16,43.21 101.55,42.6 101.55,41.475 102.24,40.785 105.985,40.785 106.175,40.975 106.175,42.75 105.715,43.21
  region net GND: 107.335,19.21 107.085,18.96 107.085,17.26 107.56,16.785 110.96,16.785 111.385,17.21 111.385,19.085 111.26,19.21
  pour cut-out: 110.05,21.75 110.025,21.725 110.25,21.725 110.25,22.75 110.05,22.95
  pour cut-out: 103.2,25.425 103.2,24.35 103.275,24.275 103.45,24.275 103.45,25.35 103.485,25.385 103.098,25.385
  pour cut-out: 109.9,24.35 110.15,24.35 110.05,24.45 110.05,25.525 109.975,25.525 109.9,25.45
  pour cut-out: 110.025,33.175 109.975,33.125 109.975,31.925 110.368,31.925 110.403,31.961 110.05,32.314 110.05,33.225
  pour cut-out: 31.7,24 31.7,23.525 31.781,23.444 32.004,23.444 32.004,24.02 31.989,24.035 31.954,24 31.675,24
  pour cut-out: 93.025,34.5 93.025,33.775 93.05,33.75 93.05,34.475
  pour cut-out: 80.55,25.775 80.548,25.773 80.548,25.002 80.927,25.002 80.95,25.025 80.525,25.45 80.525,25.75
  pour cut-out: 78.325,29.3 78.325,28.7 79.5,28.7 79.525,28.725 79.5,28.75 79.5,29.325 78.325,29.325 78.3,29.3
  pour cut-out: 78.475,32.325 78.475,31.725 78.45,31.7 78.475,31.675 79.5,31.675 79.5,32.325
  pour cut-out: 72.15,8.25 72.15,7.75 72.191,7.791 73.348,7.791 73.348,8.202 73.275,8.275 72.2,8.275
  pour cut-out: 44.7,50.825 44.675,50.85 44.675,51.575 44.525,51.425 44.625,51.325 44.625,50.825
  pour cut-out: 31.1,32.625 31.1,33.025 31.4,33.025 31.55,32.875 31.55,32.75 31.25,32.75 31.175,32.675
  pour cut-out: 32.025,33.625 31.95,33.55 31.95,33.475 32.1,33.325 32.175,33.325 32.175,33.625
  pour cut-out: 25.8,33.975 25.95,33.975 25.95,33.9 25.925,33.875 25.75,33.875 25.75,33.925
  pour cut-out: 27.575,34.125 27.8,34.125 27.8,33.875 27.775,33.85 27.75,33.875 27.6,33.875 27.6,34.1
  pour cut-out: 26.425,33.65 26.5,33.65 26.5,33.55 26.425,33.55
  pour cut-out: 26.35,33.975 26.525,33.975 26.525,33.9 26.475,33.85 26.375,33.85 26.375,33.95
  region net BC_I2C_EXP_SDA: 107.11,43.21 106.86,42.96 106.86,41.26 107.335,40.785 110.735,40.785 111.16,41.21 111.16,43.085 111.035,43.21
  region net VMCU: 102.175,19.2 101.925,18.95 101.925,17.25 102.4,16.775 105.8,16.775 106.225,17.2 106.225,19.075 106.1,19.2
  pour cut-out: 61.65,36.025 61.425,36.025 60.925,35.525 60.85,35.6 60.85,35.7 61,35.7 61.475,36.175
  pour cut-out: 41.075,46.95 41.125,46.9 41.125,46.5 41.55,46.5 41.6,46.55 41.425,46.725 41.425,47.1
  pour cut-out: 41.25,48.1 41.225,48.075 41.225,47.6 41.525,47.6 41.475,47.65 41.475,48.15 41.35,48.15 41.325,48.125
  pour cut-out: 40.05,40.075 40.05,40.175 40.55,40.675 40.5,40.725 40.225,40.725 40.225,40.575 39.85,40.2
  pour cut-out: 9.625,55.525 10.875,55.525 10.85,55.5 10.85,55.45 9.625,55.45 9.6,55.475
  pour cut-out: 23.95,32.4 23.95,32.05 24.1,32.05 24.1,32.4
  pour cut-out: 21.7,27.266 22.2,27.266 22.2,26.1 21.7,26.1
  region net N17710582: 10.542,26.275 10.542,29.5 3.462,29.5 3.462,26.275
  region net N17710582: 3.458,7.725 3.458,5.542 4.5,4.5 10.538,4.5 10.538,7.725
Signal Layer 3:
  pour cut-out: 36.575,54.8 38.05,54.8 38.05,54.475 38,54.425 37.975,54.45 36.575,54.45 36.575,54.75 36.6,54.775
  pour cut-out: 41.1,48.2 41.175,48.125 41.175,47.475 41.3,47.475 41.225,47.55 41.225,48.2 41.125,48.2
  pour cut-out: 92.018,31.557 91.925,31.464 91.925,30.975 92.05,30.975 92.018,31.007 92.018,31.543 91.95,31.475
  pour cut-out: 81.075,34.725 82.075,35.725 82.119,35.725 82.119,35.47 81.224,34.575 81.175,34.575 81.175,34.625
  pour cut-out: 80.15,48.525 80.15,47.85 80.425,47.85 80.425,48.5 80.375,48.55 80.35,48.525
  pour cut-out: 48.225,6.25 51.1,6.25 51.3,6.05 51.3,3.375 48.2,3.375 48.125,3.45 48.25,3.575 48.25,6.15
  pour cut-out: 64.375,3.525 64.275,3.425 64.2,3.5 51.225,3.5 51.225,6.225 51.275,6.275 64.375,6.275
  pour cut-out: 59.175,10.45 59.9,9.725 59.6,9.425 59.175,9.85 59.175,10.4
  pour cut-out: 61.625,13.2 61.575,13.15 61.575,11.9 61.65,11.9 61.675,11.925 61.675,13.225 61.625,13.225 61.6,13.2
  pour cut-out: 70.025,13.3 70.025,11.975 70.35,11.975 70.125,12.2 70.125,13.35
  pour cut-out: 54.3,51.3 54.1,51.1 54.1,50.7 54.125,50.7 54.3,50.525 54.373,50.598 54.498,50.598 54.498,51.152 54.35,51.3 54.275,51.3
  pour cut-out: 60.9,45.55 60.5,45.15 60.5,44.8 60.55,44.8 60.675,44.675 61.025,45.025 61.025,45.4 60.875,45.55
  pour cut-out: 83.075,45.975 83.05,45.95 83.05,44.75 83.225,44.75 83.225,45.975 83.1,45.975
  pour cut-out: 74.875,21.225 74.925,21.175 74.75,21.175 74.75,22.175 74.875,22.3
  pour cut-out: 42,6.6 45.625,6.6 45.65,6.575 45.475,6.4 45.475,5.975 42.125,5.975 41.975,6.125 41.975,6.625
  pour cut-out: 37.925,6.5 37.95,6.475 37.925,6.45 37.925,6.25 36.875,6.25 36.85,6.275 36.85,6.5
  pour cut-out: 86.125,24.75 86.425,25.05 87.025,25.05 87.025,24.62 87.098,24.547 86.926,24.375 86.25,24.375 86.25,24.575 86.075,24.75
  pour cut-out: 78.35,25.375 78.5,25.375 78.9,24.975 78.727,24.802 78.572,24.802 78.572,25.103 78.325,25.35
  pour cut-out: 51.325,26.525 51.35,26.5 51.35,25.35 50.6,25.35 50.65,25.4 50.65,26.5
  pour cut-out: 44.525,30.35 47.875,30.35 47.875,29.875 44.625,29.875 44.5,30 44.5,30.4
  pour cut-out: 81.35,52.7 81.35,51.875 81.425,51.8 81.475,51.85 81.7,51.85 81.7,52.575 81.575,52.7 81.525,52.65 81.4,52.65
  pour cut-out: 67.9,28.65 67.9,28.075 67.275,28.075 67.275,28.65
  pour cut-out: 50.625,32.3 52.3,32.3 52.325,32.325 52.325,32.425 50.625,32.425 50.575,32.375
  pour cut-out: 54,25.975 54.1,25.875 54.175,25.95 54.175,28.55 53.95,28.55 54,28.5 54,28.45
  pour cut-out: 39.7,32.95 39.7,32.025 39.65,31.975 39.65,32.95
  pour cut-out: 46.4,39.35 49.6,39.35 49.6,39.425 46.4,39.425 46.35,39.475
  pour cut-out: 43.8,37.675 45.075,37.675 45.075,37.775 45.05,37.8 43.8,37.8
  pour cut-out: 60.525,32.9 60.525,31.675 60.45,31.75 60.45,32.9
  pour cut-out: 62.125,34.6 62.125,33.625 62.1,33.6 62.075,33.625 62.075,34.625
  pour cut-out: 61.15,40.225 61.15,38.5 61.1,38.45 61,38.55 61,40.325
  pour cut-out: 50.525,43.625 50.525,42.35 50.5,42.325 50.275,42.55 50.275,43.65 50.475,43.85
  pour cut-out: 39.075,54.775 39.175,54.675 45.55,54.675 45.55,54.425 45.3,54.175 44.975,54.5 39.2,54.5
  pour cut-out: 49.35,54.625 53.125,54.625 53.175,54.575 52.95,54.35 52.95,54.325 49.525,54.325 49.325,54.525
  pour cut-out: 68.725,45.725 68.7,45.7 68.7,43.875 68.6,43.875 68.5,43.975 68.575,44.05 68.575,45.725
  pour cut-out: 72.625,39.95 73.325,39.95 73.325,40 73.25,40.075 72.7,40.075
  pour cut-out: 65.525,29.975 65.525,30.05 66.225,30.75 66.15,30.825 66.05,30.825 66.05,30.8 65.4,30.15
  pour cut-out: 72,33.75 71.975,33.725 71.975,31 71.925,31 71.875,31.05 71.875,33.7
  pour cut-out: 42.825,21.5 42.825,20.55 42.65,20.375 42.65,21.6
  pour cut-out: 29.275,25.25 29.3,25.225 29.3,24.125 29.55,24.125 29.6,24.175 29.45,24.325 29.45,25.375
  pour cut-out: 52.025,29.85 52.025,28.875 52.05,28.9 52.1,28.9 52.1,29.775
  pour cut-out: 38.95,32.95 38.95,32.975 38.925,32.95 38.9,32.95
  pour cut-out: 33.8,36.175 33.8,35.05 33.825,35.025 33.85,35.05 33.925,35.05 33.925,36.125 33.875,36.175
Signal Layer 4:
  pour cut-out: 41.825,25.05 42.075,24.8 42.075,24.625 41.7,24.625 41.425,24.9 41.425,25.05
  pour cut-out: 48.5,44.825 49.025,44.3 48.925,44.2 48.65,44.475 48.55,44.475 48.55,44.725 48.45,44.825
  pour cut-out: 42.055,45.689 42.516,46.15 42.675,46.15 42.675,46 42.775,45.9 42.45,45.575 42.125,45.575 42.125,45.619
  pour cut-out: 46.175,47.025 46.175,46.15 46.025,46.15 45.975,46.2 46,46.225 46,47.05
  pour cut-out: 77.225,34.15 78.075,34.15 78.075,33.85 78,33.775 77.975,33.8 77.225,33.8 77.225,34.1 77.25,34.125
  pour cut-out: 76.475,39.825 76.525,39.875 77.85,39.875 77.85,39.676 77.797,39.623 77.72,39.7 76.45,39.7 76.45,39.875 76.5,39.925
  pour cut-out: 75.425,26.275 76.7,26.275 76.7,25.525 76.65,25.475 76.475,25.65 75.35,25.65 75.35,26.2
  pour cut-out: 74.8,44.95 74.883,44.867 75.601,44.867 75.601,44.651 75.575,44.625 75.55,44.65 74.875,44.65 74.875,44.9 74.825,44.95
  pour cut-out: 63.88,38.955 64.57,38.955 64.57,38.551 64.67,38.451 64.494,38.275 63.65,38.275 63.425,38.5
  pour cut-out: 55.15,51.7 55.2,51.65 55.2,50.45 55.325,50.45 55.275,50.5 55.275,51.725 55.175,51.725
  pour cut-out: 46.15,55.85 46.175,55.825 46.175,54.875 46.475,54.875 46.475,55.825 46.25,55.825
  pour cut-out: 42.375,20.3 42.95,19.725 43,19.725 43.1,19.825 42.55,20.375 42.475,20.375 42.4,20.3
  pour cut-out: 72.2,50.55 72.425,50.55 72.325,50.65 72.325,51.375 72.2,51.375 72.325,51.375 72.2,51.375
  pour cut-out: 87,57.225 86.602,56.827 86.602,56.573 86.65,56.525 87.075,56.525 87.075,57.05 86.95,57.175
  pour cut-out: 96.225,53 97.25,53 97.25,52.5 96.3,52.5 96.225,52.575
  pour cut-out: 60.95,33.5 56,33.5 55.925,33.575 55.95,33.6 55.95,33.825 60.675,33.825 60.75,33.75
  pour cut-out: 62.025,46.125 61.675,45.775 60.125,47.325 60.125,48.025
  pour cut-out: 70.3,25.625 69.625,25.625 69.575,25.675 69.7,25.8 70.375,25.8
  pour cut-out: 100.55,51.525 100.55,50.625 100.5,50.575 100.425,50.65 100.425,51.4 100.525,51.5
  pour cut-out: 62.05,35.9 61.95,35.8 61.95,33.65 61.875,33.65 61.7,33.825 61.775,33.9 61.775,35.95
  pour cut-out: 42.625,32.425 43.85,32.425 43.6,32.675 43.6,32.7 42.575,32.7 42.475,32.6
  pour cut-out: 46.525,27.05 47.725,27.05 47.85,27.175 47.775,27.25 46.475,27.25
VCC Layer 5:
  pour cut-out: 0.804,36.004 0.475,35.675 0.475,36.025
  pour cut-out: 0.8,36.125 0.45,36.475 0.45,36.125 0.675,36.125
  pour cut-out: 7.05,59.525 7.475,59.1 7.575,59.1 7.575,59.55 7.55,59.575 7.525,59.55 7.075,59.55
Bottom Layer:
  pour cut-out: 48.625,34.3 48.675,34.25 48.675,33.6 48.775,33.6 48.8,33.625 48.7,33.725 48.7,34.325
  pour cut-out: 48.499,29.699 49.051,29.699 49.6,29.15 49.575,29.125 49.575,28.925 48.875,28.925 48.499,29.301
  pour cut-out: 96.925,32.45 98.075,32.45 98.7,33.075 98.75,33.025 98.75,32.725 98.275,32.725 97.775,32.225 97.2,32.225 97.2,32.383 96.998,32.585
  pour cut-out: 92.875,34.475 92.875,33.7 92.85,33.675 92.95,33.675 92.95,34.45 92.925,34.475
  pour cut-out: 49.443,54.775 50.557,54.775 50.557,54.446 50.562,54.441 50.546,54.425 49.625,54.425 49.625,54.593
  pour cut-out: 66.511,55.802 66.511,54.862 66.542,54.831 66.744,54.831 66.744,55.74 66.667,55.818 66.652,55.802
  pour cut-out: 53.732,55.568 53.732,54.862 54.056,54.862 54.075,54.843 54.075,55.575 53.725,55.575 53.7,55.6
  pour cut-out: 53.85,55.802 53.81,55.762 53.81,55.071 54.239,55.5 65.95,55.5 65.95,56.075 65.802,56.223 65.381,55.802 53.771,55.802
  pour cut-out: 49.603,54.566 49.765,54.727 66.066,54.727 66.066,54.341 65.975,54.25 65.659,54.566
  pour cut-out: 67.369,44.571 67.425,44.514 67.425,43.825 68.15,43.825 68.175,43.85 68.175,44.475 67.475,44.475
  pour cut-out: 69.475,42.8 70,42.275 70,42.225 69.8,42.225 69.425,41.85 69.53,41.745 69.53,40.886 69.395,40.886 69.425,40.916 69.425,42.625
  pour cut-out: 69.228,36.627 69.502,36.627 69.725,36.85 70,36.575 70,36.4 69.649,36.4 69.252,36.003 69.228,36.027
  pour cut-out: 69.45,38.075 69.675,37.85 69.675,37.325 69.575,37.325 69.4,37.5 69.4,38
  pour cut-out: 55.45,36.975 55.3,36.975 55,36.675 55,36.875 55.15,36.875 55.325,37.05
  pour cut-out: 55.15,46.675 55.225,46.6 55.225,44.925 55.15,44.925 55.125,44.95 55.15,44.975
  pour cut-out: 42.975,26.925 42.975,25.375 42.95,25.35 43.025,25.35 43.025,26.875 43.075,26.925
  pour cut-out: 52.575,40.1 51.85,40.1 51.85,40.15 51.9,40.2 52.5,40.2
  pour cut-out: 49.625,42.5 49.625,40.925 49.65,40.9 49.7,40.95 49.8,40.95 49.8,42.3 49.775,42.325
  pour cut-out: 41.775,43.975 41.65,44.1 41.175,44.1
  pour cut-out: 45.9,42.875 45.825,42.8 45.825,42.825 45.8,42.85
  pour cut-out: 12.5,53.2 12.25,52.95 12.25,52.9 12.05,53.1 12.3,53.35 12.425,53.35

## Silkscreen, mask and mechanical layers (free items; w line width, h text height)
Top Overlay:
  lines w0.2: 85.2,56 86.65,56 ; 87.85,56 89.3,56
  text "19" at 70.675,58.1 h1.5
  text "1" at 85.375,58.1 h1.5
  text "19" at 88.175,58.1 h1.5
  text "1" at 102.925,58.1 h1.5
  text "5V" at 30.35,57.9 h1.2
  text "GND" at 32.4,57.9 h1.2
  text "0.0" at 35.3,57.9 h1.2
  text "0.1" at 37.9,57.9 h1.2
  text "0.2" at 40.3,57.9 h1.2
  text "0.3" at 43,57.9 h1.2
  text "0.4" at 45.6,57.9 h1.2
  text "0.5" at 48,57.9 h1.2
  text "0.6" at 50.6,57.9 h1.2
  text "0.7" at 53.1,57.9 h1.2
  text "1.0" at 55.6,57.9 h1.2
  text "1.1" at 58.2,57.9 h1.2
  text "1.2" at 60.7,57.9 h1.2
  text "1.3" at 63.25,57.9 h1.2
  text "GND" at 65.35,57.9 h1.2
  text "3V3" at 68.15,57.9 h1.2
  text "20" at 70.625,52.4 h1.5
  text "2" at 85.375,52.4 h1.5
  text "20" at 88.075,52.4 h1.5
  text "2" at 102.925,52.4 h1.5
  text "5V" at 30.2,52 h1.2
  text "GND" at 32.3,52 h1.2
  text "2.7" at 35.4,52 h1.2
  text "2.6" at 37.992,52 h1.2
  text "2.5" at 40.55,52 h1.2
  text "2.4" at 42.9,52 h1.2
  text "2.3" at 45.5,52 h1.2
  text "2.2" at 48,52 h1.2
  text "2.1" at 50.55,52 h1.2
  text "2.0" at 53.1,52 h1.2
  text "1.7" at 55.6,52 h1.2
  text "1.6" at 58.2,52 h1.2
  text "1.5" at 60.8,52 h1.2
  text "1.4" at 63.25,52 h1.2
  text "GND" at 65.3,52 h1.2
  text "3V3" at 68.2,52 h1.2
  text "SIMPLICITY" at 91.7,48.95 h1.6
  text "DEBUG" at 75.175,48.6 h1.6
  text "EFM8" at 79.605,44.57 h5.4
  text "EXP" at 102.947,43.9 h2
  text "Universal Bee" at 79.502,42.33 h2.5
  text "20" at 103.947,42.3 h1.5
  text "19" at 107.847,42.3 h1.5
  text "EFM8UB2" at 82.106,22.975 h2.1
  text "2" at 104.347,16.6 h1.5
  text "1" at 108.547,16.6 h1.5
  text "LED0" at 66.374,10.621 h2
  text "BTN1" at 39.946,9.6 h2
  text "BTN0" at 51.825,9.6 h2
  text "RESET" at 104.504,9.622 h2
  text "BAT" at 16.3,9.3 h2
  text "USB" at 20.6,9.3 h2
  text "AEM" at 24.575,9.3 h2
  text "VMCU" at 28.55,7 h1.2
  text "GND" at 32.25,7 h1.2
  text "3.0" at 35.4,7 h1.2
  text "3.1" at 37.8,7 h1.2
  text "3.2" at 40.3,7 h1.2
  text "3.3" at 42.9,7 h1.2
  text "3.4" at 45.45,7 h1.2
  text "3.5" at 48.05,7 h1.2
  text "3.6" at 50.6,7 h1.2
  text "3.7" at 53.15,7 h1.2
  text "4.0" at 55.65,7 h1.2
  text "4.1" at 58.2,7 h1.2
  text "4.2" at 60.8,7 h1.2
  text "4.3" at 63.3,7 h1.2
  text "GND" at 65.3,7 h1.2
  text "3V3" at 68.15,7 h1.2
  text "VMCU" at 28.45,1.2 h1.2
  text "GND" at 32.2,1.2 h1.2
  text "NC" at 35.3,1.2 h1.2
  text "NC" at 38,1.2 h1.2
  text "NC" at 40.5,1.2 h1.2
  text "NC" at 43.1,1.2 h1.2
  text "NC" at 45.5,1.2 h1.2
  text "RST" at 47.5,1.2 h1.2
  text "C2CK" at 50.1,1.2 h1.2
  text "C2D" at 53.15,1.2 h1.2
  text "4.7" at 55.6,1.2 h1.2
  text "4.6" at 58.2,1.2 h1.2
  text "4.5" at 60.8,1.2 h1.2
  text "4.4" at 63.25,1.2 h1.2
  text "GND" at 65.3,1.2 h1.2
  text "3V3" at 68.15,1.2 h1.2
Bottom Overlay:
  text "PCB5001B Rev A01" at 1.32,34.29 h1 r90
  text "SPI_CS" at 112.75,28.226 h1.7
  text "SPI_SCK" at 113.85,25.726 h1.7
  text "SPI_MISO" at 114.45,23.176 h1.7
  text "SPI_MOSI" at 114.375,21.126 h1.7
  text "BOARD INFO" at 19.8,15.775 h1.52
  text "BAT" at 7.4,4.1 h1.52
  text "GND" at 7.45,1.45 h1.52
Top Solder:
  the board outline again, w0.8
Bottom Solder:
  the board outline again, w0.8
Board Outline:
  lines w0.1: 0,1.2 ccw(c1.2,1.2) 1.2,0 ; 0,1.2 ccw(c1.2,1.2) 1.2,0 ; 0,1.2 0,58.8 ; 0,1.2 0,58.8 ; 0,58.8 cw(c1.2,58.8) 1.2,60 ; 0,58.8 cw(c1.2,58.8) 1.2,60 ; 1.2,0 113.8,0 ; 1.2,0 113.8,0 ; 1.2,60 113.8,60 ; 1.2,60 113.8,60 ; 113.8,0 ccw(c113.8,1.2) 115,1.2 ; 113.8,0 ccw(c113.8,1.2) 115,1.2 ; 113.8,60 cw(c113.8,58.8) 115,58.8 ; 113.8,60 cw(c113.8,58.8) 115,58.8 ; 115,1.2 115,58.8 ; 115,1.2 115,58.8
Route Tool Path:
  lines w0.1: 8.5,0 1.2,0 cw(c1.2,1.2) 0,1.2 0,58.8 cw(c1.2,58.8) 1.2,60 8.5,60 ; 15.5,0 56.5,0 ; 15.5,60 56.5,60 ; 63.5,0 94.5,0 ; 63.5,60 94.5,60 ; 101.5,0 113.8,0 ccw(c113.8,1.2) 115,1.2 115,58.8 ccw(c113.8,58.8) 113.8,60 101.5,60 ; -2.4,1.2 ccw(c1.2,1.2) 1.2,-2.4 ; -2.4,1.2 ccw(c1.2,1.2) 1.2,-2.4 ; -2.4,1.2 -2.4,58.8 cw(c1.2,58.8) 1.2,62.4 ; 1.2,-2.4 8.5,-2.4 1.2,-2.4 ; 1.2,62.4 8.5,62.4 1.2,62.4 ; 113.8,-2.4 ccw(c113.8,1.2) 117.4,1.2 ; 113.8,-2.4 ccw(c113.8,1.2) 117.4,1.2 ; 113.8,-2.4 101.5,-2.4 113.8,-2.4 ; 113.8,62.4 cw(c113.8,58.8) 117.4,58.8 ; 113.8,62.4 cw(c113.8,58.8) 117.4,58.8 ; 113.8,62.4 101.5,62.4 113.8,62.4 ; 117.4,1.2 117.4,58.8 ; 117.4,1.2 117.4,58.8 ; 15.5,-2.4 56.5,-2.4 15.5,-2.4 ; 15.5,62.4 56.5,62.4 15.5,62.4 ; 63.5,-2.4 94.5,-2.4 63.5,-2.4 ; 63.5,62.4 94.5,62.4 63.5,62.4
Top Component Center (Mech19):
  the board outline again, w0.1
Bottom Component Center:
  the board outline again, w0.1
Assembly Drawing Frame (Top):
  lines w0.2: -75.055,-40.875 -73.43,-40.875 ; -75.055,5.8 -73.43,5.8 ; -75.055,52.475 -73.43,52.475 ; -20.406,-89.125 -20.406,-87.525 ; -20.406,99.175 -20.406,100.775 ; 32.619,-89.125 32.619,-87.525 ; 32.619,99.175 32.619,100.775 ; 85.644,-89.125 85.644,-87.525 ; 85.644,99.175 85.644,100.775 ; 138.67,-89.125 138.67,-87.525 ; 138.67,99.175 138.67,100.775 ; 191.695,-40.85 193.32,-40.85 ; 191.695,5.825 193.32,5.825 ; 191.695,52.5 193.32,52.5 ; 193.32,-89.125 -75.055,-89.125 -75.055,100.775 193.32,100.775 193.32,-89.1 ; -73.43,-87.525 -73.43,99.175 191.695,99.175 191.695,-87.525 -73.43,-87.525
  text "5" at -48.083,99.804 h0.5
  text "1" at 167.624,99.794 h0.5
  text "2" at 111.801,99.79 h0.5
  text "4" at 5.582,99.694 h0.5
  text "3" at 60.57,99.694 h0.5
  text "D" at 192.41,75.734 h0.5
  text "D" at -74.402,75.614 h0.5
  text "C" at 192.318,29.368 h0.5
  text "C" at -74.474,29.3 h0.5
  text "B" at 192.502,-17.274 h0.5
  text "B" at -74.314,-18.048 h0.5
  text "A" at 192.41,-62.919 h0.5
  text "A" at -74.43,-63.952 h0.5
  text "3" at 60.964,-88.516 h0.5
  text "4" at 8.082,-88.543 h0.5
  text "2" at 112.8,-88.541 h0.5
  text "1" at 167.702,-88.59 h0.5
  text "5" at -48.128,-88.62 h0.5
Title Block (Top):
  drawing of 27 lines, arcs and shapes, not listed
  text "Board Title" at 122.095,-62.575 h2.5
  text "EFM8UB2 Universal Bee STK" at 123.495,-68.125 h3.5
  text "Page Title" at 122.095,-72.3 h2.5
  text "Designed:" at 89.845,-76.05 h1.7
  text "Approved:" at 106.044,-76.05 h1.7
  text "Top Assembly" at 123.495,-76.2 h3.2
  text "MRB" at 91.369,-78.55 h2.2
  text "ASN" at 107.42,-78.55 h2.2
  text "Revision" at 179.995,-79.325 h1.7
  text "Document number" at 122.095,-79.6 h2.35
  text "Size" at 89.845,-80.8 h1.7
  text "Sheet Modified Date" at 94.77,-80.8 h1.7
  text "A01" at 180.269,-82.375 h2.7
  text "BRD5001B (PCB5001B Rev A01)" at 123.495,-82.475 h3.2
  text "A4" at 90.419,-82.65 h2
  text "'.Print_Date'" at 95.344,-82.65 h2
  text "Sheet" at 179.995,-85 h1.7
  text "COPYRIGHT SILICON LABORATORIES  INC. 2022" at 94.492,-86.008 h1.7
  text "CONFIDENTIAL -SUBJECT TO TERMS OF USE" at 134.474,-86.008 h1.7
  text "1" at 181.194,-86.95 h1.7
  text "of" at 184.319,-86.95 h1.7
  text "2" at 187.045,-86.95 h1.7
Assembly Drawing Frame (Bottom):
  lines w0.2: -75.055,-40.875 -73.43,-40.875 ; -75.055,5.8 -73.43,5.8 ; -75.055,52.475 -73.43,52.475 ; -20.406,-89.125 -20.406,-87.525 ; -20.406,99.175 -20.406,100.775 ; 32.619,-89.125 32.619,-87.525 ; 32.619,99.175 32.619,100.775 ; 85.644,-89.125 85.644,-87.525 ; 85.644,99.175 85.644,100.775 ; 138.67,-89.125 138.67,-87.525 ; 138.67,99.175 138.67,100.775 ; 191.695,-40.85 193.32,-40.85 ; 191.695,5.825 193.32,5.825 ; 191.695,52.5 193.32,52.5 ; 193.32,-89.125 -75.055,-89.125 -75.055,100.775 193.32,100.775 193.32,-89.1 ; -73.43,-87.525 -73.43,99.175 191.695,99.175 191.695,-87.525 -73.43,-87.525
  text "5" at -47.684,99.864 h0.5
  text "2" at 112.147,99.804 h0.5
  text "1" at 167.78,99.798 h0.5
  text "4" at 5.948,99.733 h0.5
  text "3" at 60.92,99.702 h0.5
  text "D" at 192.703,75.77 h0.5
  text "D" at -74.06,75.574 h0.5
  text "D" at -74.06,75.574 h0.5
  text "C" at -74.166,29.365 h0.5
  text "C" at 192.643,29.363 h0.5
  text "B" at 192.797,-17.265 h0.5
  text "B" at -74.022,-18.016 h0.5
  text "A" at 192.718,-62.912 h0.5
  text "A" at -74.095,-63.932 h0.5
  text "3" at 61.301,-88.491 h0.5
  text "4" at 8.384,-88.563 h0.5
  text "2" at 113.157,-88.549 h0.5
  text "1" at 167.888,-88.576 h0.5
  text "5" at -47.776,-88.625 h0.5
Title Block (Bottom):
  drawing of 27 lines, arcs and shapes, not listed
  text "Board Title" at -3.83,-62.575 h2.5
  text "EFM8UB2 Universal Bee STK" at -5.23,-68.125 h3.5
  text "Page Title" at -3.83,-72.3 h2.5
  text "Approved:" at 12.22,-76.05 h1.7
  text "Designed:" at 28.42,-76.05 h1.7
  text "Bottom Assembly" at -5.23,-76.2 h3.2
  text "ASN" at 10.845,-78.55 h2.2
  text "MRB" at 26.895,-78.55 h2.2
  text "Revision" at -61.73,-79.325 h1.7
  text "Document number" at -3.83,-79.6 h2.35
  text "Sheet Modified Date" at 23.495,-80.8 h1.7
  text "Size" at 28.42,-80.8 h1.7
  text "A01" at -61.995,-82.375 h2.7
  text "BRD5001B (PCB5001B Rev A01)" at -5.23,-82.475 h3.2
  text "'.Print_Date'" at 22.92,-82.65 h2
  text "A4" at 27.845,-82.65 h2
  text "Sheet" at -61.73,-85 h1.7
  text "COPYRIGHT SILICON LABORATORIES  INC. 2022" at 23.658,-85.936 h1.7
  text "CONFIDENTIAL -SUBJECT TO TERMS OF USE" at -16.906,-86.024 h1.7
  text "2" at -68.78,-86.95 h1.7
  text "of" at -66.055,-86.95 h1.7
  text "2" at -62.93,-86.95 h1.7
Assembly Drawing Frame:
  lines w0.2: -82.618,-94.272 200.882,-94.272 200.882,106.203 -82.618,106.203 -82.618,-94.272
